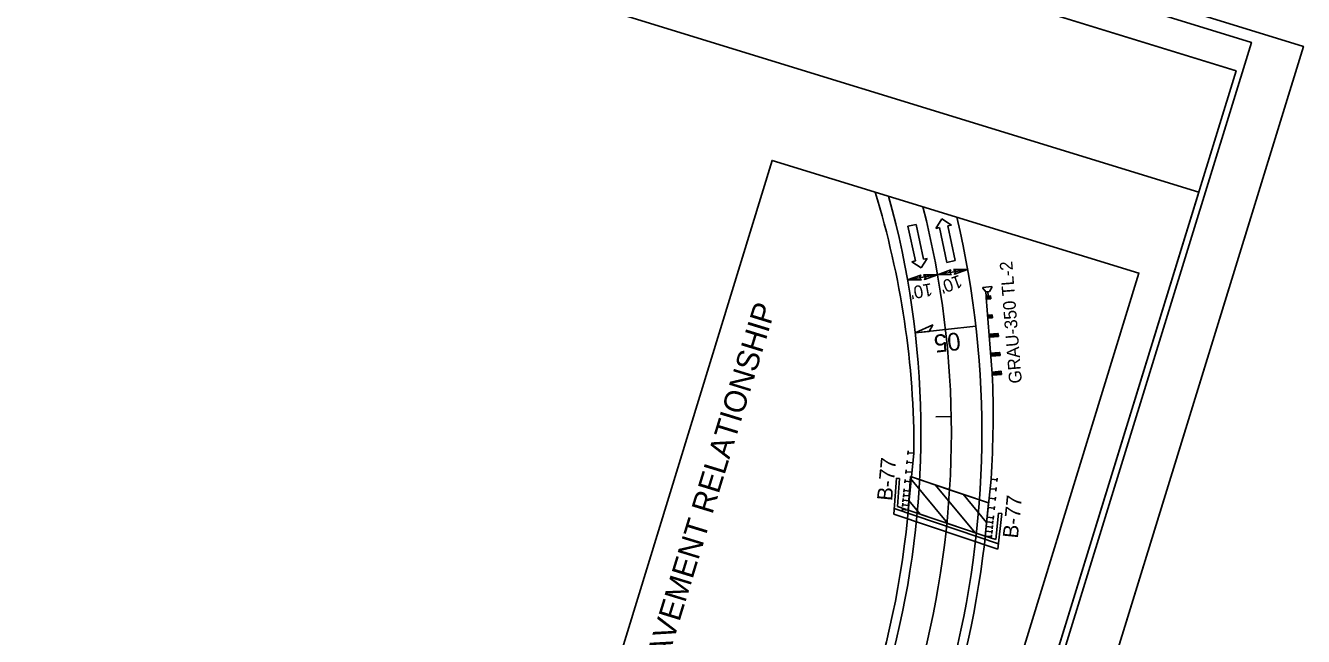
# Model space of a CAD drawing. Extents: x 1347957 to 1349499, y 1028289 to 1030503.
# Drawn here: x 1348996 to 1349499, y 1029665 to 1029906 of the extents above; entities that cross this region are included whole.
import ezdxf

# ---------------------------------------------------------------- set-up
doc = ezdxf.new("R2010")
doc.units = 0
for name, color, linetype in [('Default', 7, 'Continuous'), ('Prop Dimension', 7, 'Continuous'), ('Prop EOT', 7, 'Continuous'), ('Prop Guardrail', 7, 'Continuous'), ('Prop Guardrail Anchor Unit CELL', 7, 'Continuous'), ('Prop Horizontal Alignment', 7, 'Continuous'), ('Prop Horizontal Alignment Tick Small', 7, 'Continuous'), ('Prop Lane Arrow CELL', 7, 'Continuous'), ('Prop Roadway Bridge', 7, 'Continuous'), ('Prop Structure Anchor Unit CELL', 7, 'Continuous'), ('Prop Superelevation  Arrow CELL', 7, 'Continuous'), ('Prop Superelevation Label', 7, 'Continuous'), ('Prop Terminator CELL', 7, 'Continuous'), ('Sheet Clip Boundary CELL', 7, 'Continuous'), ('Sheet Cutting Line CELL', 7, 'Continuous'), ('Sheet Layout Plan Border', 7, 'Continuous'), ('Sheet Plan CELL', 7, 'Continuous'), ('Sheet Plan Layout CELL', 7, 'Continuous'), ('Sheet Plot Border Inside CELL', 7, 'Continuous'), ('Sheet Plot Border Outside CELL', 7, 'Continuous')]:
    doc.layers.add(name, color=color, linetype=linetype)

msp = doc.modelspace()

# ---------------------------------------------------------------- linework, layer by layer
at = {"layer": 'Default'}
for p, q in [((1349337.71, 1029713.53), (1349338.76, 1029727.66)), ((1349339.96, 1029727.57), (1349338.76, 1029727.66)), ((1349339.14, 1029716.53), (1349339.96, 1029727.57)), ((1349379.01, 1029713.94), (1349377.94, 1029703.5)), ((1349378.76, 1029699.74), (1349380.21, 1029713.82)), ((1349380.21, 1029713.82), (1349379.01, 1029713.94))]:
    msp.add_line(p, q, dxfattribs=at)
for points in [[(1349337.71, 1029713.53), (1349378.76, 1029699.74)], [(1349337.87, 1029715.69), (1349378.98, 1029701.88)], [(1349339.14, 1029716.53), (1349342.65, 1029715.35)], [(1349373.77, 1029704.9), (1349377.94, 1029703.5)]]:
    msp.add_lwpolyline(points, dxfattribs=at)
at = {"layer": 'Prop Dimension'}
msp.add_line((1349366.78, 1029809.91), (1349343.14, 1029805.76), dxfattribs=at)
msp.add_lwpolyline([(1349171.26, 1029466.55), (1349289.82, 1029852.82), (1349434.23, 1029808.5), (1349315.67, 1029422.23)], close=True, dxfattribs=at)
at = {"layer": 'Prop EOT'}
for radius, end in [(348, 15.5258), (372, 13.1925)]:
    msp.add_arc((1349000.38, 1029745.6), radius, 317.4777, end, dxfattribs=at)
at = {"layer": 'Prop Guardrail'}
for centre, radius, start, end in [((1349001.57, 1029738.87), 344.09, 359.7687, 17.1598), ((1349000.48, 1029752.31), 376.37, 356.1878, 2.5245)]:
    msp.add_arc(centre, radius, start, end, dxfattribs=at)
at = {"layer": 'Prop Guardrail Anchor Unit CELL'}
for p, q in [((1349372.75, 1029802.85), (1349376.27, 1029803.12)), ((1349372.78, 1029802.48), (1349372.75, 1029802.85)), ((1349373.92, 1029801.15), (1349372.78, 1029802.48)), ((1349375.39, 1029801.27), (1349373.92, 1029801.15)), ((1349374.06, 1029799.39), (1349373.92, 1029801.15)), ((1349374.05, 1029799.39), (1349375.86, 1029799.54)), ((1349374.14, 1029798.2), (1349374.05, 1029799.39)), ((1349375.96, 1029798.34), (1349374.05, 1029799.39)), ((1349374.1, 1029798.79), (1349376.48, 1029768.89)), ((1349374.14, 1029798.2), (1349375.86, 1029799.54)), ((1349374.78, 1029801.22), (1349374.92, 1029799.46)), ((1349376.3, 1029802.75), (1349375.39, 1029801.27)), ((1349375.96, 1029798.34), (1349375.86, 1029799.54)), ((1349376.3, 1029802.75), (1349376.27, 1029803.12)), ((1349374.14, 1029798.2), (1349375.96, 1029798.34)), ((1349374.64, 1029791.92), (1349376.46, 1029792.06)), ((1349374.74, 1029790.72), (1349374.64, 1029791.92)), ((1349376.56, 1029790.86), (1349374.64, 1029791.92)), ((1349374.74, 1029790.72), (1349376.46, 1029792.06)), ((1349374.74, 1029790.72), (1349376.56, 1029790.86)), ((1349376.56, 1029790.86), (1349376.46, 1029792.06)), ((1349375.24, 1029784.44), (1349378.87, 1029784.73)), ((1349375.34, 1029783.24), (1349375.24, 1029784.44)), ((1349377.15, 1029783.39), (1349375.24, 1029784.44)), ((1349375.34, 1029783.24), (1349377.06, 1029784.58)), ((1349375.34, 1029783.24), (1349378.97, 1029783.53)), ((1349377.15, 1029783.39), (1349377.06, 1029784.58)), ((1349377.06, 1029784.58), (1349378.97, 1029783.53)), ((1349378.87, 1029784.73), (1349377.15, 1029783.39)), ((1349378.97, 1029783.53), (1349378.87, 1029784.73)), ((1349375.84, 1029776.96), (1349379.47, 1029777.25)), ((1349375.93, 1029775.77), (1349375.84, 1029776.96)), ((1349377.75, 1029775.91), (1349375.84, 1029776.96)), ((1349375.93, 1029775.77), (1349377.65, 1029777.11)), ((1349375.93, 1029775.77), (1349379.56, 1029776.06)), ((1349377.75, 1029775.91), (1349377.65, 1029777.11)), ((1349377.65, 1029777.11), (1349379.56, 1029776.06)), ((1349379.47, 1029777.25), (1349377.75, 1029775.91)), ((1349379.56, 1029776.06), (1349379.47, 1029777.25)), ((1349376.43, 1029769.49), (1349380.06, 1029769.78)), ((1349376.53, 1029768.29), (1349376.43, 1029769.49)), ((1349378.34, 1029768.44), (1349376.43, 1029769.49)), ((1349376.53, 1029768.29), (1349378.25, 1029769.63)), ((1349376.53, 1029768.29), (1349380.16, 1029768.58)), ((1349378.34, 1029768.44), (1349378.25, 1029769.63)), ((1349378.25, 1029769.63), (1349380.16, 1029768.58)), ((1349380.06, 1029769.78), (1349378.34, 1029768.44)), ((1349380.16, 1029768.58), (1349380.06, 1029769.78))]:
    msp.add_line(p, q, dxfattribs=at)
at = {"layer": 'Prop Horizontal Alignment'}
msp.add_arc((1349000.38, 1029745.6), 360, 317.4777, 14.313, dxfattribs=at)
at = {"layer": 'Prop Horizontal Alignment Tick Small'}
msp.add_line((1349360.33, 1029751.93), (1349354.33, 1029751.82), dxfattribs=at)
at = {"layer": 'Prop Lane Arrow CELL'}
for p, q in [((1349354.28, 1029826.07), (1349356.65, 1029829.8)), ((1349356.65, 1029829.8), (1349360.44, 1029827.39)), ((1349343.31, 1029826.95), (1349346.54, 1029827.64)), ((1349346.23, 1029813.26), (1349343.31, 1029826.95)), ((1349346.54, 1029827.64), (1349349.46, 1029813.95)), ((1349355.74, 1029826.38), (1349354.28, 1029826.07)), ((1349358.66, 1029812.69), (1349355.74, 1029826.38)), ((1349360.44, 1029827.39), (1349358.97, 1029827.07)), ((1349358.97, 1029827.07), (1349361.89, 1029813.38)), ((1349350.93, 1029814.26), (1349348.55, 1029810.54)), ((1349349.46, 1029813.95), (1349350.93, 1029814.26)), ((1349344.77, 1029812.95), (1349346.23, 1029813.26)), ((1349348.55, 1029810.54), (1349344.77, 1029812.95)), ((1349361.89, 1029813.38), (1349358.66, 1029812.69))]:
    msp.add_line(p, q, dxfattribs=at)
at = {"layer": 'Prop Roadway Bridge'}
for p, q in [((1349359.68, 1029723.14), (1349344.35, 1029728.29)), ((1349358.98, 1029709.86), (1349344.29, 1029727.51)), ((1349369.82, 1029706.22), (1349354.2, 1029724.99)), ((1349359.68, 1029723.14), (1349374.97, 1029718.01)), ((1349348.14, 1029713.51), (1349343.69, 1029718.85)), ((1349374.26, 1029710.27), (1349365.04, 1029721.34)), ((1349358.62, 1029709.99), (1349343.43, 1029715.09)), ((1349358.62, 1029709.99), (1349373.77, 1029704.9))]:
    msp.add_line(p, q, dxfattribs=at)
msp.add_lwpolyline([(1349343.43, 1029715.09), (1349344.35, 1029728.29), (1349374.97, 1029718.01), (1349373.77, 1029704.9)], close=True, dxfattribs=at)
for radius, start, end in [(344.4, 327.9454, 357.1202), (375.6, 329.0842, 355.7877)]:
    msp.add_arc((1349000.38, 1029745.6), radius, start, end, dxfattribs=at)
at = {"layer": 'Prop Structure Anchor Unit CELL'}
for p, q in [((1349343.2, 1029737.03), (1349343.34, 1029738.4)), ((1349342.83, 1029733.3), (1349342.97, 1029734.67)), ((1349345.29, 1029733.75), (1349342.9, 1029733.98)), ((1349345.66, 1029737.48), (1349343.27, 1029737.72)), ((1349343.43, 1029715.09), (1349345.66, 1029737.48)), ((1349342.46, 1029729.57), (1349342.59, 1029730.94)), ((1349344.91, 1029730.02), (1349342.53, 1029730.25)), ((1349341.72, 1029722.11), (1349341.85, 1029723.47)), ((1349342.09, 1029725.84), (1349342.22, 1029727.21)), ((1349344.54, 1029726.28), (1349342.16, 1029726.52)), ((1349373.77, 1029704.9), (1349376.01, 1029727.28)), ((1349375.64, 1029723.55), (1349378.03, 1029723.31)), ((1349376.01, 1029727.28), (1349378.4, 1029727.05)), ((1349377.96, 1029722.63), (1349378.1, 1029724)), ((1349378.33, 1029726.36), (1349378.47, 1029727.73)), ((1349341.34, 1029718.37), (1349341.48, 1029719.74)), ((1349343.8, 1029718.82), (1349341.41, 1029719.06)), ((1349341.53, 1029720.24), (1349341.67, 1029721.61)), ((1349343.99, 1029720.69), (1349341.6, 1029720.92)), ((1349344.17, 1029722.55), (1349341.78, 1029722.79)), ((1349375.27, 1029719.82), (1349377.65, 1029719.58)), ((1349377.59, 1029718.9), (1349377.72, 1029720.27)), ((1349340.97, 1029714.64), (1349341.11, 1029716.01)), ((1349343.43, 1029715.09), (1349341.04, 1029715.33)), ((1349341.16, 1029716.51), (1349341.3, 1029717.88)), ((1349343.62, 1029716.96), (1349341.23, 1029717.19)), ((1349374.89, 1029716.09), (1349377.28, 1029715.85)), ((1349377.21, 1029715.17), (1349377.35, 1029716.54)), ((1349374.15, 1029708.63), (1349376.53, 1029708.39)), ((1349374.33, 1029710.49), (1349376.72, 1029710.25)), ((1349374.52, 1029712.36), (1349376.91, 1029712.12)), ((1349376.47, 1029707.71), (1349376.6, 1029709.07)), ((1349376.65, 1029709.57), (1349376.79, 1029710.94)), ((1349376.84, 1029711.44), (1349376.98, 1029712.8)), ((1349373.77, 1029704.9), (1349376.16, 1029704.66)), ((1349373.96, 1029706.76), (1349376.35, 1029706.52)), ((1349376.09, 1029703.97), (1349376.23, 1029705.34)), ((1349376.28, 1029705.84), (1349376.42, 1029707.21))]:
    msp.add_line(p, q, dxfattribs=at)
at = {"layer": 'Prop Superelevation  Arrow CELL'}
msp.add_line((1349370.01, 1029787.59), (1349346.16, 1029784.88), dxfattribs=at)
msp.add_lwpolyline([(1349346.16, 1029784.88), (1349353.04, 1029788.08), (1349351.67, 1029785.51)], close=True, dxfattribs=at)
at = {"layer": 'Prop Terminator CELL'}
for points in [[(1349360.44, 1029807.86), (1349354.96, 1029807.84), (1349360.14, 1029809.73), (1349359.63, 1029808.66)], [(1349361.3, 1029809.89), (1349366.78, 1029809.91), (1349361.6, 1029808.02), (1349362.11, 1029809.09)], [(1349348.62, 1029805.78), (1349343.14, 1029805.76), (1349348.33, 1029807.65), (1349347.81, 1029806.58)], [(1349349.48, 1029807.82), (1349354.96, 1029807.84), (1349349.78, 1029805.96), (1349350.29, 1029807.02)]]:
    msp.add_lwpolyline(points, close=True, dxfattribs=at)
at = {"layer": 'Sheet Clip Boundary CELL'}
msp.add_lwpolyline([(1349045.75, 1028502.32), (1349457.8, 1029840.32), (1348656.43, 1030087.11), (1348600.72, 1029906.23), (1348398.6, 1029968.48), (1348042.26, 1028811.35)], close=True, dxfattribs=at)
at = {"layer": 'Sheet Cutting Line CELL'}
msp.add_line((1349003.55, 1028288.8), (1349499.03, 1029897.73), dxfattribs=at)
at = {"layer": 'Sheet Layout Plan Border'}
msp.add_lwpolyline([(1349045.75, 1028502.32), (1349457.8, 1029840.32), (1348656.43, 1030087.11), (1348600.72, 1029906.23), (1348398.6, 1029968.48), (1348042.26, 1028811.35)], close=True, dxfattribs=at)
at = {"layer": 'Sheet Plan CELL'}
for points in [[(1348469.03, 1030197.17), (1348027.54, 1028763.57), (1349031.04, 1028454.54), (1349472.52, 1029888.11)], [(1349031.04, 1028454.54), (1348027.56, 1028763.54), (1348410.13, 1030005.96), (1348553.55, 1029961.8), (1348612.44, 1030152.98), (1349472.52, 1029888.11)]]:
    msp.add_lwpolyline(points, close=True, dxfattribs=at)
at = {"layer": 'Sheet Plan Layout CELL'}
msp.add_lwpolyline([(1348027.56, 1028763.54), (1349031.04, 1028454.54), (1349472.51, 1029888.1), (1348671.14, 1030134.89), (1348600.72, 1029906.23), (1348398.6, 1029968.48)], close=True, dxfattribs=at)
at = {"layer": 'Sheet Plot Border Inside CELL'}
msp.add_lwpolyline([(1348988.26, 1028307.11), (1349478.58, 1029899.31), (1348470.32, 1030209.82), (1347979.99, 1028617.61)], close=True, dxfattribs=at)
at = {"layer": 'Sheet Plot Border Outside CELL'}
msp.add_lwpolyline([(1349003.55, 1028288.8), (1349499.03, 1029897.73), (1348452.53, 1030220.01), (1347957.05, 1028611.07)], close=True, dxfattribs=at)

# ---------------------------------------------------------------- texts
at = {"layer": 'Prop Dimension'}
for s, height, rotation, p in [('GRAU-350 TL-2', 5, 94.5582, (1349388.2, 1029765.19)), ("10'", 5, 189.9557, (1349352.48, 1029804.54)), ("10'", 5, 200.035, (1349363.53, 1029807.89)), ('SKETCH SHOWING BRIDGE / PAVEMENT RELATIONSHIP', 8.75, 72.9373, (1349197.77, 1029490.02)), ('B-77', 6, 84.3192, (1349337.04, 1029718.59)), ('B-77', 6, 84.3192, (1349386.56, 1029703.81))]:
    msp.add_text(s, height=height, rotation=rotation, dxfattribs=at).set_placement(p)
at = {"layer": 'Prop Superelevation Label'}
msp.add_text('05', height=7, rotation=186.4819, dxfattribs=at).set_placement((1349363.57, 1029785.21))

doc.saveas('drawing.dxf')
